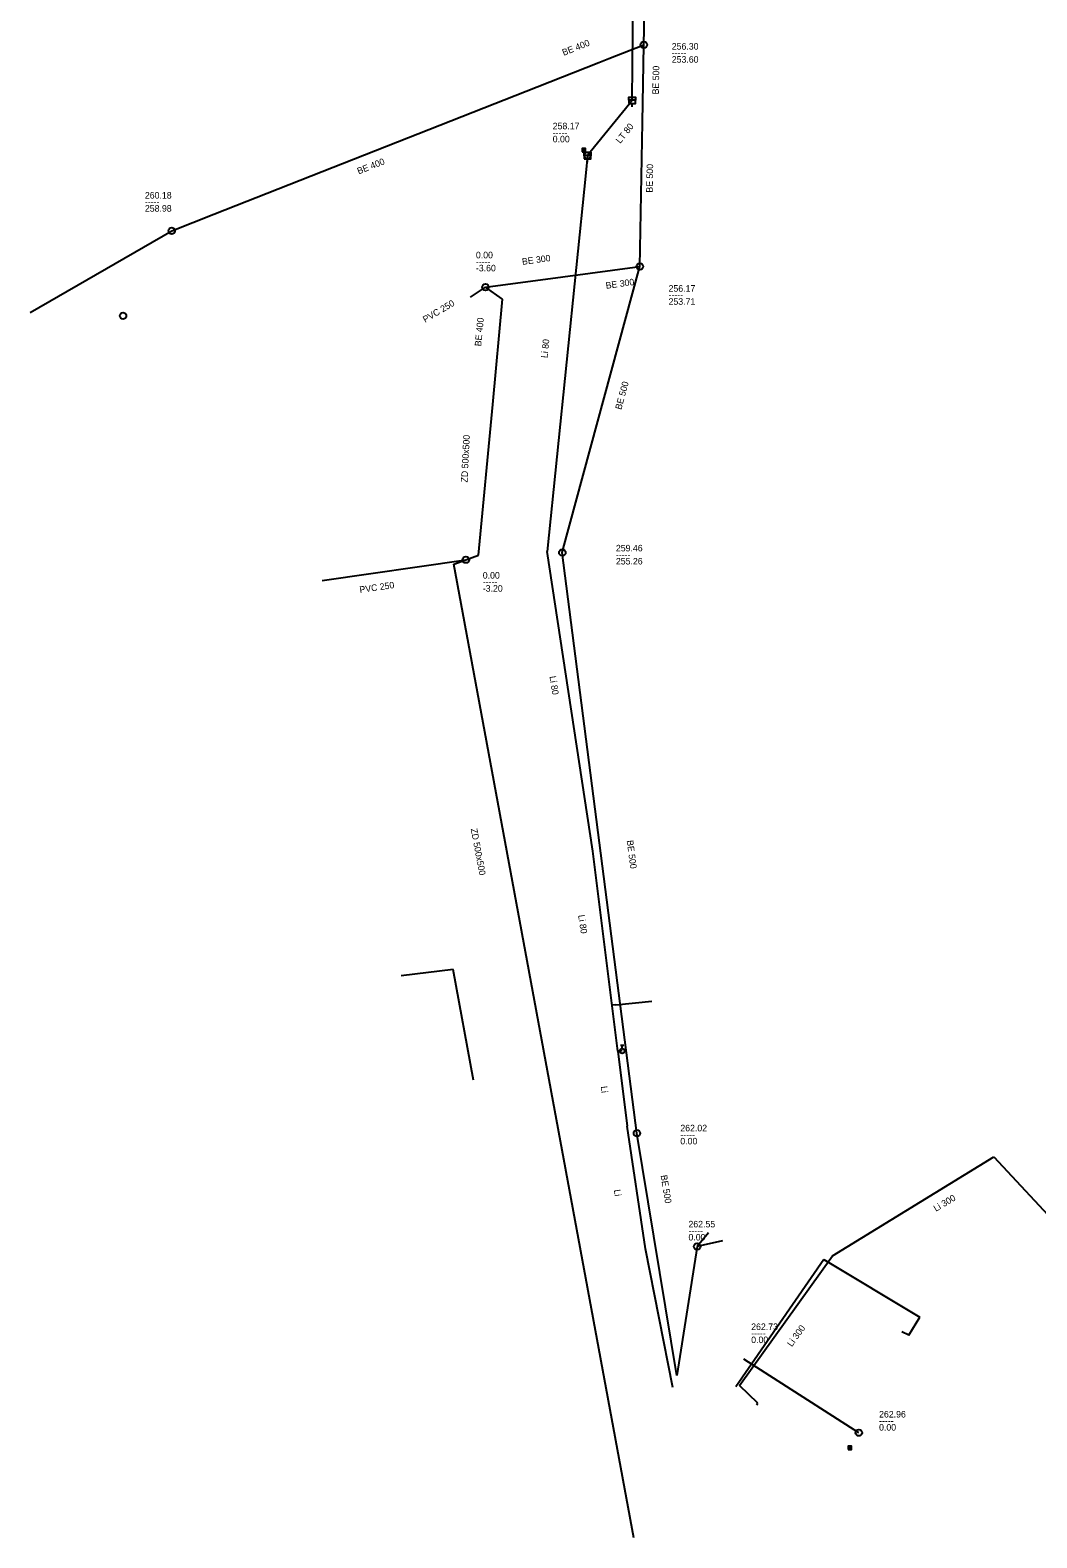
# Model space of a CAD drawing. Extents: x -647357 to -646700, y -1072205 to -1071664.
# Drawn here: x -647356.5 to -647202.6, y -1072012.1 to -1071781.5 of the extents above; entities that cross this region are included whole.
import ezdxf

# ---------------------------------------------------------------- set-up
doc = ezdxf.new("R2010")
doc.units = 0
for name, color, linetype in [('Level 19', 7, 'Continuous'), ('Level 20', 7, 'Continuous'), ('Level 21', 7, 'Continuous'), ('Level 24', 7, 'Continuous'), ('Level 29', 7, 'Continuous'), ('Level 40', 7, 'Continuous'), ('Level 41', 7, 'Continuous'), ('Level 44', 7, 'Continuous'), ('Level 45', 7, 'Continuous'), ('Level 46', 7, 'Continuous')]:
    doc.layers.add(name, color=color, linetype=linetype)

msp = doc.modelspace()

# ---------------------------------------------------------------- linework, layer by layer
at = {"layer": 'Level 19'}
for p, q in [((-647291.86, -1071925.19), (-647299.84, -1071926.15)), ((-647288.77, -1071942.1), (-647291.86, -1071925.19)), ((-647266.99, -1071930.59), (-647267.56, -1071930.66)), ((-647266.99, -1071930.59), (-647261.48, -1071930.03)), ((-647235.2, -1071969.55), (-647248.65, -1071988.99)), ((-647235.2, -1071969.55), (-647220.54, -1071978.33)), ((-647222.19, -1071981.08), (-647220.54, -1071978.33)), ((-647222.19, -1071981.08), (-647223.3, -1071980.59))]:
    msp.add_line(p, q, dxfattribs=at)
at = {"layer": 'Level 20'}
for p, q in [((-647264.49, -1071792.27), (-647264.3, -1071766.69)), ((-647264.49, -1071792.27), (-647264.87, -1071792.75)), ((-647264.87, -1071792.75), (-647270.91, -1071800.2)), ((-647271.33, -1071800.72), (-647271.6, -1071803.38)), ((-647270.91, -1071800.2), (-647271.33, -1071800.72)), ((-647271.6, -1071803.38), (-647277.48, -1071861.29)), ((-647270.5, -1071907.08), (-647277.48, -1071861.29)), ((-647266.68, -1071937.68), (-647270.5, -1071907.08)), ((-647266.48, -1071937.66), (-647266.68, -1071937.68)), ((-647266.68, -1071937.68), (-647265.27, -1071949.12)), ((-647266.04, -1071937.64), (-647266.48, -1071937.66)), ((-647262.47, -1071967.91), (-647265.27, -1071949.12)), ((-647233.9, -1071968.95), (-647209.23, -1071953.82)), ((-647209.23, -1071953.82), (-647198.86, -1071964.95)), ((-647258.28, -1071989.1), (-647262.47, -1071967.91)), ((-647248.08, -1071988.81), (-647233.9, -1071968.95)), ((-647245.29, -1071991.5), (-647248.08, -1071988.81)), ((-647245.46, -1071991.75), (-647245.29, -1071991.5))]:
    msp.add_line(p, q, dxfattribs=at)
at = {"layer": 'Level 21'}
for p, q in [((-647266.29, -1071936.765), (-647265.79, -1071936.765)), ((-647266.04, -1071937.265), (-647266.04, -1071936.765))]:
    msp.add_line(p, q, dxfattribs=at)
msp.add_circle((-647266.04, -1071937.64), 0.375, dxfattribs=at)
at = {"layer": 'Level 29'}
for p, q in [((-647264.49, -1071793.27), (-647264.49, -1071792.77)), ((-647271.33, -1071801.72), (-647271.33, -1071801.22))]:
    msp.add_line(p, q, dxfattribs=at)
for points in [[(-647264.99, -1071792.27), (-647264.99, -1071791.77), (-647263.99, -1071791.77), (-647263.99, -1071792.27)], [(-647271.83, -1071800.72), (-647271.83, -1071800.22), (-647270.83, -1071800.22), (-647270.83, -1071800.72)]]:
    msp.add_lwpolyline(points, dxfattribs=at)
for points in [[(-647264.99, -1071792.77), (-647263.99, -1071792.77), (-647263.99, -1071792.27), (-647264.99, -1071792.27)], [(-647271.83, -1071801.22), (-647270.83, -1071801.22), (-647270.83, -1071800.72), (-647271.83, -1071800.72)]]:
    msp.add_lwpolyline(points, close=True, dxfattribs=at)
at = {"layer": 'Level 40'}
for p, q in [((-647262.71, -1071783.78), (-647262.31, -1071762.66)), ((-647268.08, -1071785.89), (-647262.71, -1071783.78)), ((-647262.94, -1071795.66), (-647262.71, -1071783.78)), ((-647279.02, -1071790.21), (-647269.6, -1071786.49)), ((-647269.6, -1071786.49), (-647268.08, -1071785.89)), ((-647328.43, -1071809.68), (-647279.02, -1071790.21)), ((-647263.33, -1071817.7), (-647262.94, -1071795.66)), ((-647334.89, -1071812.23), (-647328.43, -1071809.68)), ((-647356.53, -1071824.72), (-647334.89, -1071812.23)), ((-647275.18, -1071861.44), (-647263.33, -1071817.7)), ((-647275.09, -1071819.27), (-647263.33, -1071817.7)), ((-647286.93, -1071820.85), (-647275.09, -1071819.27)), ((-647289.24, -1071822.38), (-647286.93, -1071820.85)), ((-647284.33, -1071822.68), (-647286.93, -1071820.85)), ((-647285.8, -1071838.81), (-647284.33, -1071822.68)), ((-647288.01, -1071861.85), (-647285.8, -1071838.81)), ((-647263.77, -1071950.19), (-647275.18, -1071861.44)), ((-647311.9, -1071865.7), (-647289.94, -1071862.52)), ((-647291.75, -1071863.21), (-647289.94, -1071862.52)), ((-647264.26, -1072012.09), (-647291.75, -1071863.21)), ((-647289.94, -1071862.52), (-647288.01, -1071861.85)), ((-647257.69, -1071987.24), (-647263.77, -1071950.19)), ((-647254.58, -1071967.54), (-647257.69, -1071987.24)), ((-647229.86, -1071996.01), (-647247.44, -1071984.78))]:
    msp.add_line(p, q, dxfattribs=at)
at = {"layer": 'Level 41'}
for centre in [(-647262.71, -1071783.78), (-647271.33, -1071800.7), (-647334.89, -1071812.23), (-647263.33, -1071817.7), (-647286.93, -1071820.85), (-647342.33, -1071825.23), (-647275.18, -1071861.44), (-647289.94, -1071862.52), (-647263.77, -1071950.19), (-647254.58, -1071967.54), (-647229.86, -1071996.01)]:
    msp.add_circle(centre, 0.5, dxfattribs=at)
at = {"layer": 'Level 45'}
for p in [(-647252.84, -1071965.44), (-647250.7, -1071966.68)]:
    msp.add_line(p, (-647254.58, -1071967.54), dxfattribs=at)
at = {"layer": 'Level 46'}
for p, q in [((-647272.16, -1071799.9), (-647271.66, -1071799.9)), ((-647231.5, -1071998.33), (-647231, -1071998.33))]:
    msp.add_line(p, q, dxfattribs=at)
for points in [[(-647272.16, -1071800.151), (-647271.66, -1071800.151), (-647271.66, -1071799.649), (-647272.16, -1071799.649)], [(-647231.5, -1071998.581), (-647230.999, -1071998.581), (-647230.999, -1071998.079), (-647231.5, -1071998.079)]]:
    msp.add_lwpolyline(points, close=True, dxfattribs=at)

# ---------------------------------------------------------------- texts
at = {"layer": 'Level 24'}
for s, rotation, p in [('LT 80', 51.349, (-647266.33, -1071798.96)), ('Li 80', 84.202, (-647277.45, -1071831.72)), ('Li 80', 278.667, (-647277.14, -1071880.37)), ('Li 80', 278.667, (-647272.77, -1071916.89)), ('Li', 277.026, (-647269.31, -1071943.07)), ('Li', 278.476, (-647267.3, -1071958.89)), ('Li 300', 30.86, (-647218.07, -1071962.25)), ('Li 300', 54.473, (-647240.09, -1071982.96))]:
    msp.add_text(s, height=1, rotation=rotation, dxfattribs=at).set_placement(p)
at = {"layer": 'Level 44'}
for s, rotation, p in [('BE 400', 21.549, (-647274.97, -1071785.48)), ('BE 500', 88.891, (-647260.43, -1071791.38)), ('BE 400', 21.507, (-647306.31, -1071803.61)), ('BE 500', 88.908, (-647261.37, -1071806.4)), ('BE 300', 7.601, (-647281.28, -1071817.44)), ('BE 300', 7.604, (-647268.48, -1071821.1)), ('PVC 250', 30.683, (-647296.14, -1071826.31)), ('BE 400', 84.507, (-647287.59, -1071829.92)), ('BE 500', 74.841, (-647266.16, -1071839.65)), ('ZD 500x500', 87.049, (-647289.68, -1071850.73)), ('PVC 250', 8.24, (-647306.11, -1071867.62)), ('ZD 500x500', 280.545, (-647289.19, -1071903.69)), ('BE 500', 277.326, (-647265.34, -1071905.47)), ('BE 500', 279.319, (-647260.16, -1071956.68))]:
    msp.add_text(s, height=1, rotation=rotation, dxfattribs=at).set_placement(p)
for s, p in [('-----', (-647258.45, -1071785.52)), ('256.30', (-647258.45, -1071784.52)), ('253.60', (-647258.45, -1071786.52)), ('258.17', (-647276.65, -1071796.7)), ('0.00', (-647276.65, -1071798.7)), ('-----', (-647276.65, -1071797.7)), ('-----', (-647338.99, -1071808.3)), ('260.18', (-647338.99, -1071807.3)), ('258.98', (-647338.99, -1071809.3)), ('0.00', (-647288.39, -1071816.43)), ('-----', (-647288.39, -1071817.43)), ('-3.60', (-647288.39, -1071818.43)), ('-----', (-647258.94, -1071822.54)), ('256.17', (-647258.94, -1071821.54)), ('253.71', (-647258.94, -1071823.54)), ('259.46', (-647266.99, -1071861.25)), ('-----', (-647266.99, -1071862.25)), ('255.26', (-647266.99, -1071863.25)), ('0.00', (-647287.34, -1071865.41)), ('-----', (-647287.34, -1071866.41)), ('-3.20', (-647287.34, -1071867.41)), ('262.02', (-647257.14, -1071949.93)), ('0.00', (-647257.14, -1071951.93)), ('-----', (-647257.14, -1071950.93)), ('-----', (-647255.9, -1071965.62)), ('262.55', (-647255.9, -1071964.62)), ('0.00', (-647255.9, -1071966.62)), ('0.00', (-647246.31, -1071982.31)), ('-----', (-647246.31, -1071981.31)), ('262.73', (-647246.31, -1071980.31)), ('262.96', (-647226.76, -1071993.69)), ('0.00', (-647226.76, -1071995.69)), ('-----', (-647226.76, -1071994.69))]:
    msp.add_text(s, height=1, dxfattribs=at).set_placement(p)

doc.saveas('drawing.dxf')
